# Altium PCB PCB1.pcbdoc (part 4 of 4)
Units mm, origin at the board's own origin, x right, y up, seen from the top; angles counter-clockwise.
Board outline 96.27 x 122.17 mm, 6 copper layers (Top Layer, Inner1, Inner2, Inner3, Inner4, Bottom Layer); 169 components, 166 nets, 787 pads, 477 vias.
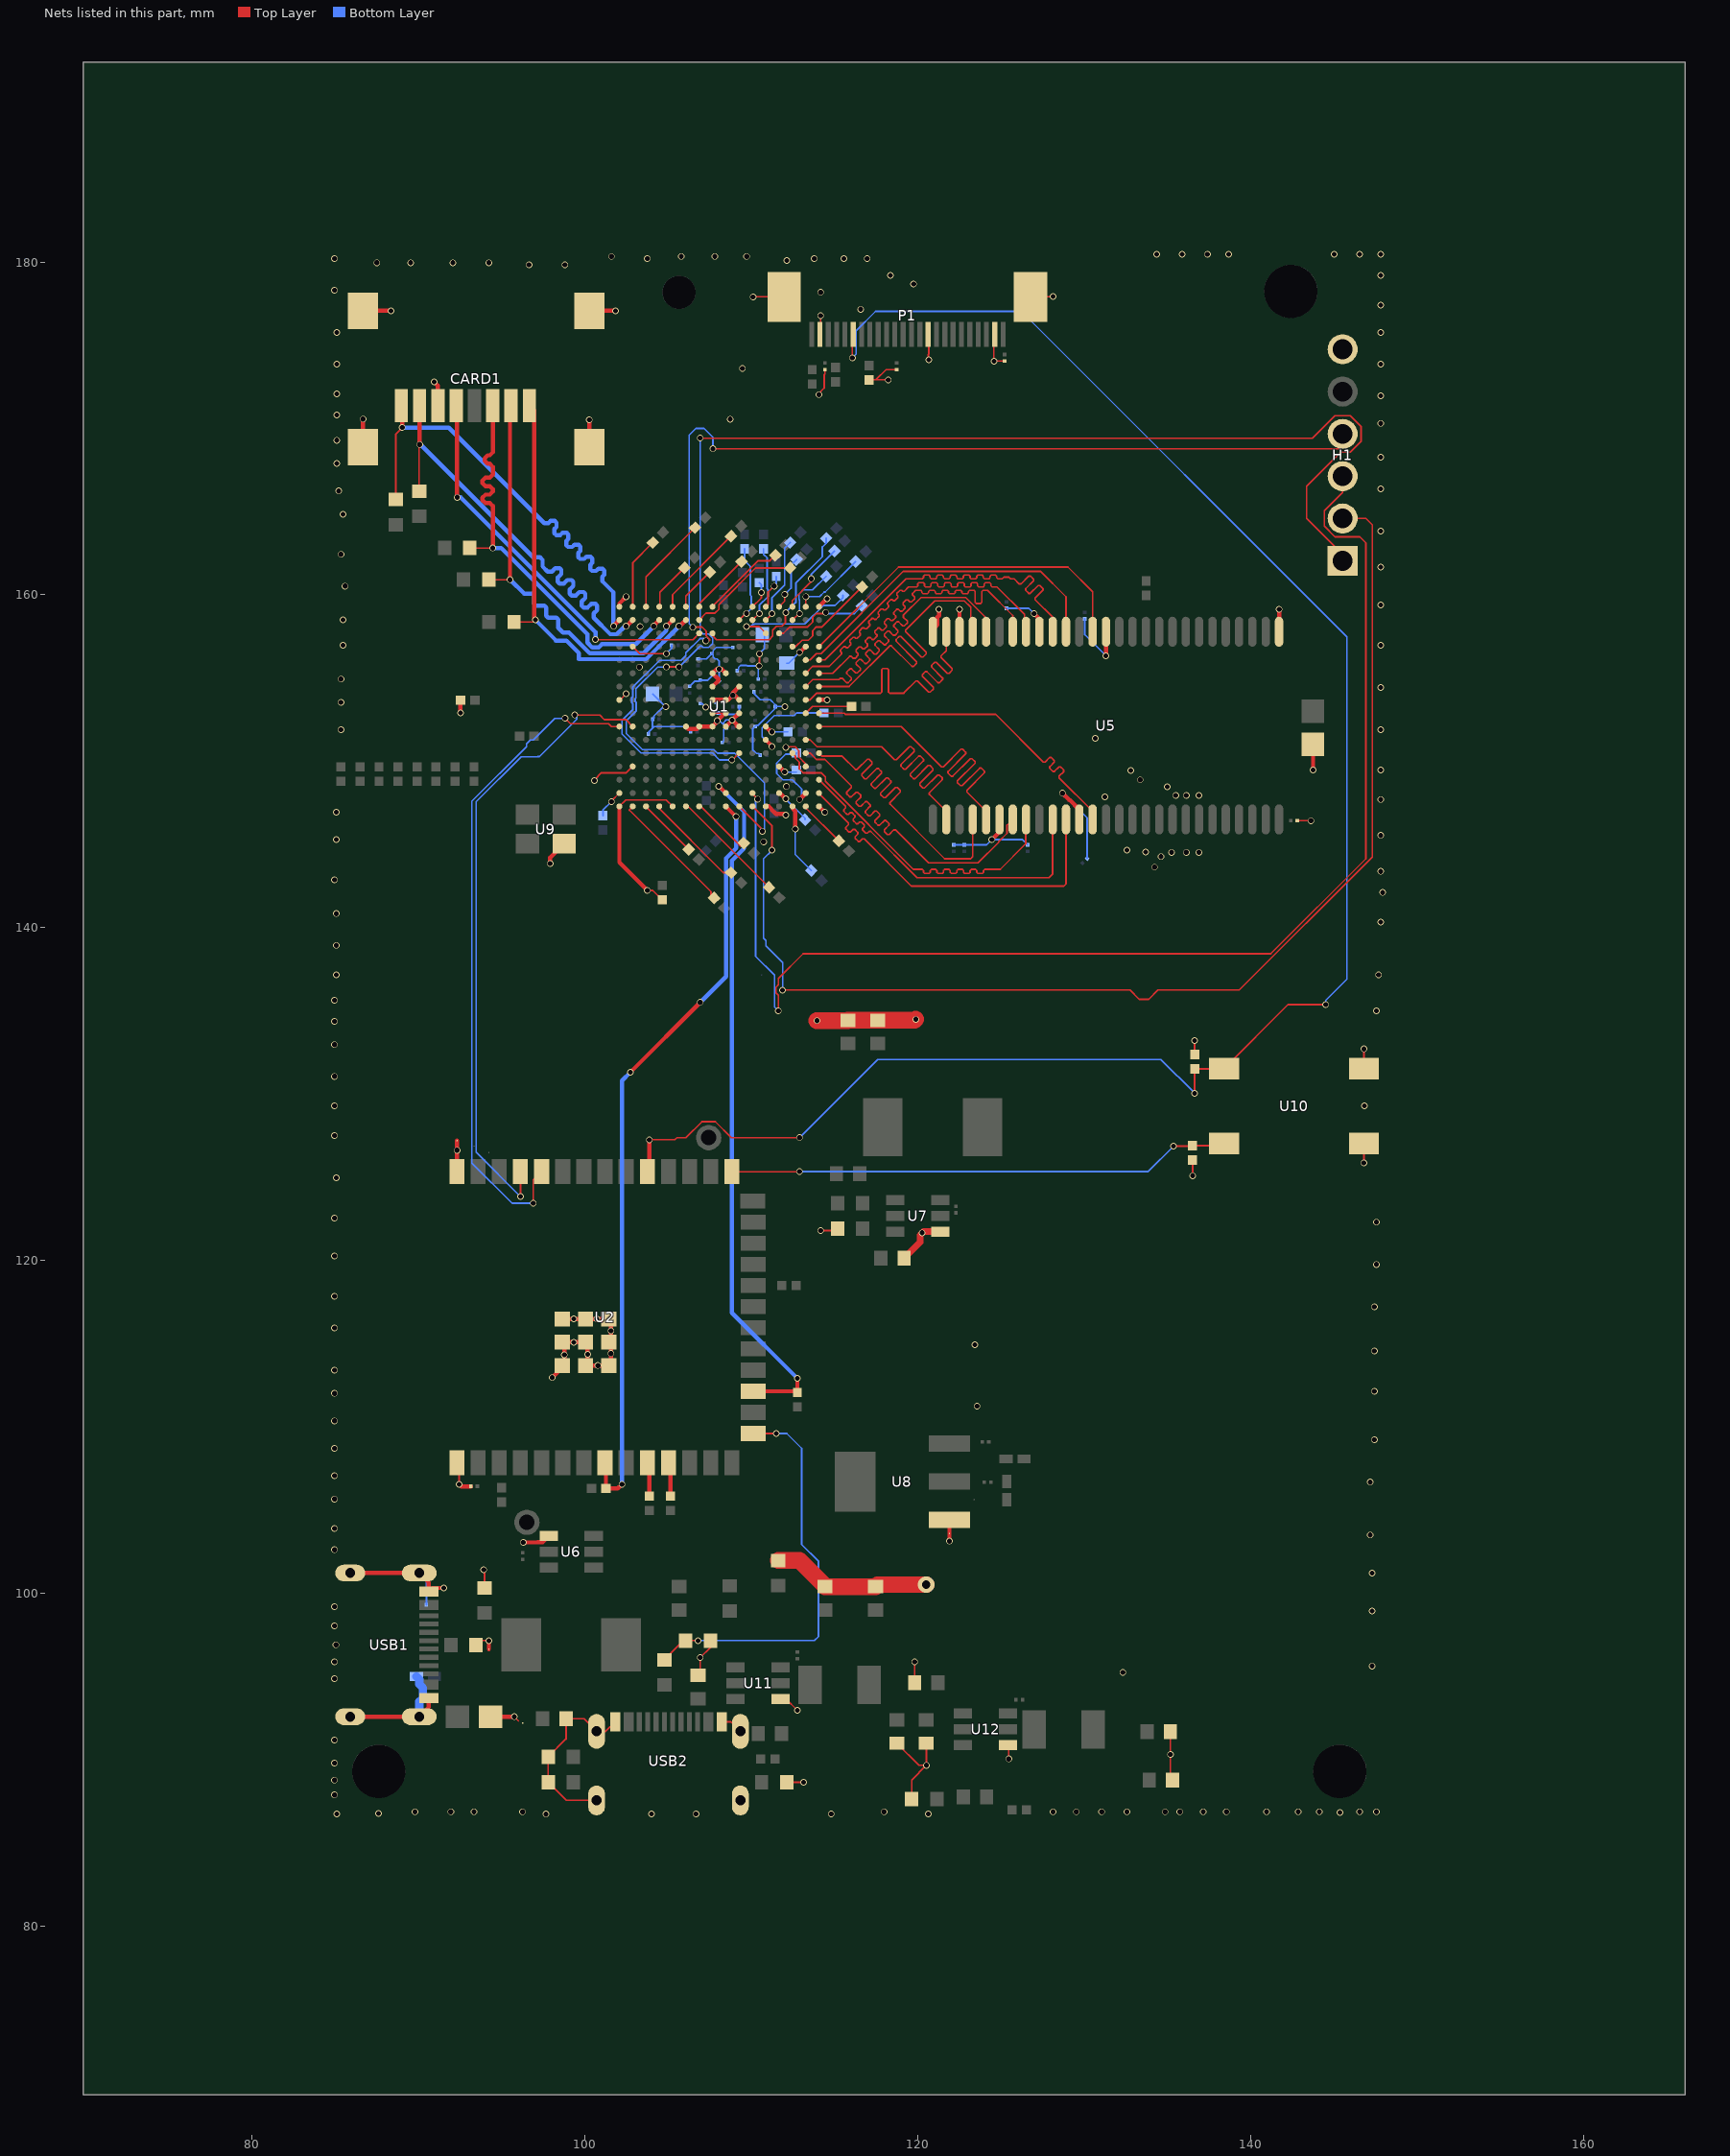
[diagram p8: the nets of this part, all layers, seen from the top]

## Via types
v1: diameter 0.4, hole 0.3, Top Layer to Bottom Layer, 448 vias
v2: diameter 1, hole 0.5, Top Layer to Bottom Layer, 28 vias
v3: diameter 0.5, hole 0.3, Top Layer to Bottom Layer, 1 vias

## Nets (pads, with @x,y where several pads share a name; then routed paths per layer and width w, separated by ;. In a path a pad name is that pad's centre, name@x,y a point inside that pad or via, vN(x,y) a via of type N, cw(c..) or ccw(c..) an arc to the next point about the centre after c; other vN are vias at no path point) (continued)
GND: C8.2 C10.2 C11.2 C12.2 C13.2 C14.2 C15.1 C16.1 C17.1 C20.1 C22.1 C23.1 C26.1 C27.1 C28.1 C33.1 C34.2 C35.2 C37.2 C39.2 C40.2 C41.2 C42.2 C43.2 C44.2 C45.2 C46.2 C47.2 C48.2 C49.2 C50.2 C51.2 C52.2 C53.2 C54.2 C55.2 C56.2 C57.2 C58.2 C59.2 C61.2 C62.2 C63.2 C66.1 C67.1 C68.1 C71.1 C72.1 C73.1 C74.2 C75.1 C76.2 CARD1.6 CARD1.9 CARD1.10 CARD1.11 CARD1.12 H1.6 P1.2 P1.15 P1.23 P1.25 P1.26 pad.55@92.324,127.195 pad.55@94.234,96.647 pad.55@96.266,92.202 pad.55@121.914,103.597 R9.1 R10.1 R12.1 R14.1 R24.1 R25.1 R35.2 R36.2 R37.2 R40.1 R42.2 R43.2 R45.1 R46.1 U1.A1 U1.A16 U1.D2 U1.D15 U1.F8 U1.F9 U1.G8 U1.G10 U1.H1 U1.H8 U1.H9 U1.H10 U1.H16 U1.J8 U1.J9 U1.J10 U1.K6 U1.K7 U1.K8 U1.K9 U1.K10 U1.N2 U1.N15 U1.T1 U1.T5 U1.T12 U1.T16 U2.1 U2.40 U2.41 U5.6 U5.12 U5.28 U5.41 U5.46 U5.52 U5.54 U6.4 U7.4 U8.1 U9.2 U10.2 U10.4 U11.4 U12.4 USB1.1 USB1.2 USB1.3 USB1.4 USB1.A1B12 USB1.B1A12 USB2.1 USB2.2 USB2.3 USB2.4 USB2.A1B12 USB2.B1A12 | length 203.8
  Top Layer w0.1: U2.1@92.324,107.836 92.451,107.709 v1(92.451,106.553) ; R10.1@93.463,96.901 93.717,97.155 v1(94.234,97.155) ; v1(93.931,101.415) 93.98,101.366 R9.1@93.98,100.321 ; v1(95.758,92.583) 96.012,92.329 ; v1(100.584,148.844) 100.584,148.886 101.005,149.307 102.495,149.307 U1.N2@102.877,149.689 ; USB2.3@100.709,87.554 98.891,87.554 R42.2@97.799,88.646 R43.2@97.799,90.17 98.871,91.242 C20.1@98.871,92.456 99.956,92.456 USB2.1@100.709,91.703 101.254,91.703 USB2.A1B12@101.829,92.278 ; U1.T1@102.077,147.289 102.459,147.671 104.895,147.671 U1.T5@105.277,147.289 ; 102.235,153.797 102.477,154.039 v1(102.477,154.051) ; U1.D2@102.877,156.889 103.302,156.464 103.512,156.464 103.519,156.471 104.635,156.471 104.642,156.464 v1@104.902,156.464 ; v1(103.759,142.24) 104.088,142.24 R25.1@104.648,141.68 ; C66.1@106.807,95.061 106.934,95.188 v1(106.934,96.139) 107.56,96.765 R45.1@107.56,97.155 ; U1.J8@107.677,152.889 U1.J9@108.42,152.889 ; USB2.B1A12@108.229,92.278 108.774,92.278 USB2.2@109.349,91.703 ; v1(110.109,177.909) P1.26@111.979,177.909 ; v1(110.477,155.737) 110.49,155.75 v1(110.49,156.464) ; U11.4@111.766,93.637 112.103,93.637 v1(112.776,92.964) ; v1(112.077,150.841) 112.216,150.841 112.246,150.871 112.635,150.871 112.859,150.647 112.859,150.258 113.277,149.84 U1.N15@113.277,149.689 ; R40.1@112.132,88.646 v1(113.157,88.646) ; v1(114.063,172.035) 114.063,172.102 114.39,172.429 114.39,173.245 114.427,173.282 C34.2@114.427,173.541 ; P1.2@114.135,175.655 114.173,175.694 v1(114.173,176.784) ; v1(114.173,121.793) 115.071,121.793 R14.1@115.198,121.92 ; R35.2@117.094,172.922 117.491,172.922 ; v1(118.237,172.922) 117.491,172.922 ; C68.1@118.745,90.994 120.077,89.662 v1(120.523,89.662) ; C35.2@118.745,173.541 118.11,173.541 117.491,172.922 ; R46.1@119.643,87.63 119.643,88.782 v1(120.523,89.662) ; C71.1@119.823,94.615 v1(119.823,95.885) ; C67.1@120.523,90.994 v1(120.523,89.662) ; P1.15@120.631,175.654 120.667,175.617 120.667,174.455 120.65,174.437 v1@120.65,174.117 ; P1.23@124.636,175.652 124.587,175.603 v1(124.587,174.045) 124.591,174.049 C74.2@125.222,174.049 ; U12.4@125.429,90.871 125.476,90.824 v1(125.476,90.043) ; P1.25@126.781,177.916 128.132,177.916 v1(128.143,177.927) ; C73.1@135.193,91.694 v1(135.193,90.323) 135.193,88.9 C72.1@135.32,88.773 ; v1(136.525,125.095) R37.2@136.525,126.036 ; R36.2@136.652,132.386 v1(136.652,133.223) ; C14.2@142.816,146.431 v1(143.637,146.431) ; v1(146.812,125.857) 146.821,125.866 U10.4@146.821,127.036 ; U10.2@146.821,131.536 v1(146.821,132.715)
  Top Layer w0.254: USB1.4@85.903,92.581 USB1.2@90.052,92.581 90.627,93.156 USB1.B1A12@90.627,93.701 ; USB1.3@85.903,101.221 USB1.1@90.052,101.221 90.627,100.646 USB1.A1B12@90.627,100.101 90.848,100.321 v1(91.526,100.321) ; CARD1.10@86.672,168.874 v1(86.672,170.565) ; CARD1.9@86.672,177.074 v1(88.357,177.074) ; v1(90.945,172.801) 91.172,172.574 CARD1.6@91.172,171.374 ; pad.55@92.324,127.195 v1(92.324,126.623) 92.324,125.463 U2.40@92.451,125.336 ; v1(92.451,106.553) 92.578,106.426 C17.1@93.15,106.426 ; v1(92.531,152.902) R24.1@92.531,153.67 ; pad.55@94.234,96.647 v1(94.234,97.155) ; C33.1@94.345,92.583 v1(95.758,92.583) ; v1(96.299,103.058) 97.161,103.058 97.171,103.068 97.466,103.068 U6.4@97.837,103.439 ; v1(97.917,143.861) 97.917,144.202 U9.2@98.763,145.048 ; v1(98.045,112.96) 98.771,113.686 v1(98.771,114.339) 98.771,115.086 v1(99.347,115.086) 100.171,115.086 v1(100.171,114.364) 100.171,113.686 v1(100.791,113.686) 101.571,113.686 v1(101.571,114.408) v1(101.571,115.77) 101.571,116.486 v1(100.722,116.486) U2.41@100.044,116.486 v1(99.347,116.486) U2.41@98.771,116.486 ; CARD1.11@100.272,168.874 v1(100.272,170.523) ; CARD1.12@100.272,177.074 v1(101.854,177.074) ; U1.T1@102.077,147.289 102.077,143.922 v1(103.759,142.24) ; U1.A1@102.077,159.289 102.077,159.481 v1(102.489,159.893) ; U1.K6@106.077,152.089 106.218,151.948 106.736,151.948 U1.K7@106.877,152.089 U1.K8@107.677,152.089 107.964,152.376 v1(107.964,152.432) 108.42,152.889 U1.J9@108.477,152.889 ; U1.H8@107.677,153.689 U1.H9@108.477,153.689 108.628,153.689 v1(108.896,153.957) ; U1.G8@107.677,154.489 108.029,154.841 108.029,154.937 U1.F8@107.677,155.289 107.931,155.543 v1(108.068,155.543) 108.223,155.543 U1.F9@108.477,155.289 ; U1.K9@108.477,152.089 108.856,152.468 v1(108.856,152.481) ; U1.K10@109.121,152.117 109.121,152.215 v1(108.856,152.481) ; U1.J10@109.277,152.889 109.264,152.889 v1(108.856,152.481) ; U1.H10@109.277,153.689 109.009,153.957 v1(108.896,153.957) ; U1.G10@109.277,154.489 108.896,154.108 v1(108.896,153.957) ; U1.T12@110.877,147.289 111.064,147.289 111.218,147.135 111.218,147.099 111.487,146.83 112.001,146.83 v1(112.074,146.757) ; v1@112.903,156.591 112.979,156.591 U1.D15@113.277,156.889 ; U1.T16@114.077,147.289 v1(114.427,146.939) ; U1.H16@114.077,153.689 v1(114.554,153.691) ; U1.A16@114.077,159.289 v1(114.554,159.766) ; U5.54@120.918,157.915 121.189,158.186 121.189,158.657 121.285,158.753 v1(121.285,159.131) ; v1(121.914,103.134) pad.55@121.914,103.597 U8.1@121.914,104.409 ; U5.52@122.518,157.915 v1(122.518,159.131) ; v1(124.46,145.288) 124.918,145.746 U5.6@124.918,146.504 ; v1(127,158.877) 127.318,158.559 U5.46@127.318,157.788 ; v1(128.702,148.082) 129.101,147.683 129.137,147.683 129.718,147.102 U5.12@129.718,146.504 ; v1(131.318,156.337) U5.41@131.318,157.915 ; U5.28@141.718,157.788 141.732,157.802 v1(141.732,159.131) ; v1(143.764,149.479) C8.2@143.764,151.019
  Top Layer w0.4: C26.1@119.191,120.142 120.142,121.093 120.142,121.524 v1@120.269,121.651 ; v1(120.269,121.666) v1@120.269,121.651 ; U7.4@121.365,121.732 120.35,121.732 v1@120.269,121.651
  Top Layer w1: R12.1@111.633,101.972 112.912,101.972 C23.1@114.489,100.395 ; v1(113.951,134.411) 115.804,134.411 C27.1@115.824,134.431 C28.1@117.602,134.431 119.826,134.431 v1(119.888,134.493) ; C23.1@114.427,100.395 C23.1@114.489,100.395 ; v2(120.515,100.522) 117.602,100.522 C22.1@117.475,100.395 C23.1@114.489,100.395
  Bottom Layer w0.1: USB1.1@90.052,101.221 90.483,100.791 C76.2@90.483,99.314 ; C51.2@103.818,151.638 103.818,151.749 104.072,152.003 ; C61.2@104.075,154.051 104.089,154.051 v1(104.864,153.276) 104.711,153.276 104.155,152.721 104.155,152.567 104.115,152.527 C56.2@104.072,152.527 104.072,152.003 ; v1(104.901,156.465) 105.215,156.779 C37.2@105.215,156.972 ; C41.2@106.299,154.5 106.612,154.813 106.875,154.813 C62.2@106.934,154.872 107.397,154.872 v1(108.068,155.543) ; C54.2@106.358,151.765 106.032,152.091 104.16,152.091 104.072,152.003 ; C63.2@106.807,156.151 107.315,156.151 C50.2@107.628,156.464 ; C45.2@106.934,153.475 107.043,153.475 v1(107.263,153.256) ; C46.2@107.882,153.543 107.935,153.49 107.935,152.991 C57.2@108.018,152.908 108.113,152.813 109.188,152.813 ; v1(107.964,152.432) 108.103,152.432 108.346,152.19 ; C42.2@108.068,154.826 v1(108.068,155.543) ; C53.2@108.263,151.13 108.346,151.213 108.346,151.919 108.446,152.019 C49.2@108.517,152.019 108.346,152.19 ; C39.2@108.898,156.845 107.898,156.845 107.711,156.658 107.711,156.547 C50.2@107.628,156.464 ; C43.2@109.152,155.448 109.235,155.531 109.235,155.642 109.353,155.76 109.731,155.76 109.754,155.737 v1(110.477,155.737) 110.422,155.682 C40.2@110.422,154.94 ; C47.2@109.288,153.289 109.288,152.913 109.188,152.813 ; C44.2@110.168,154.178 110.168,154.067 110.534,153.701 111.146,153.701 111.447,153.4 C55.2@111.447,153.289 ; v1(110.49,156.464) 110.806,156.78 C58.2@110.806,157.607 ; C48.2@110.549,150.368 110.443,150.474 110.323,150.474 110.088,150.709 110.088,151.93 C52.2@110.236,152.078 110.319,152.161 110.43,152.161 111.447,153.178 C55.2@111.447,153.289 ; v1@112.014,153.289 C55.2@111.447,153.289 ; C59.2@112.141,155.894 112.254,155.894 v1(112.903,156.544) ; C10.2@122.174,144.975 C11.2@122.809,144.975 124.147,144.975 v1(124.46,145.288) 126.306,145.288 C12.2@126.619,144.975 ; C16.1@125.349,159.19 126.687,159.19 v1(127,158.877) ; v1(128.702,148.082) 130.186,146.598 C13.2@130.186,144.156 ; C15.1@130.048,158.555 130.048,157.607 v1(131.318,156.337) ; C50.2@107.628,156.464 107.711,156.381 107.711,156.27 107.829,156.152 107.94,156.152 108.068,156.024 v1(108.068,155.543) ; 108.346,152.19 108.346,152.331 108.496,152.481 v1(108.856,152.481) 109.188,152.813
  Bottom Layer w0.5: C75.1@89.879,94.996 90.052,94.823 90.052,94.54 90.28,94.312 90.28,93.71 90.052,93.482 USB1.2@90.052,92.581
  other v1: 85.09,86.741 97.663,86.729 104.013,86.741 106.68,86.741 114.808,86.741 120.65,86.741 87.608,86.762 145.379,86.827 89.789,86.868 91.948,86.868 93.345,86.868 96.266,86.868 117.983,86.868 128.143,86.868 129.54,86.868 131.064,86.868 132.588,86.868 134.874,86.868 135.763,86.868 137.16,86.868 138.557,86.868 140.97,86.868 142.875,86.868 144.145,86.868 146.558,86.868 147.574,86.868 84.963,87.884 84.963,88.773 84.963,89.789 84.963,91.186 84.963,94.869 132.334,95.25 147.32,95.631 84.963,95.885 85.048,96.901 84.963,98.044 147.32,98.933 84.963,99.187 147.32,101.219 84.963,102.616 147.193,103.505 84.963,103.886 84.963,105.664 147.193,106.68 84.963,107.061 84.963,108.712 147.447,109.22 84.963,110.363 123.571,111.252 84.963,112.014 147.447,112.141 84.963,113.411 147.447,114.554 123.444,114.935 84.963,115.951 147.447,117.221 84.963,117.856 147.574,119.761 84.963,120.269 147.574,122.301 84.963,122.555 85.069,124.968 84.963,127.508 84.963,129.286 146.86,129.286 84.963,131.064 84.963,132.969 84.963,134.366 147.574,135.001 84.963,135.636 85.069,137.16 147.701,137.16 85.069,138.938 147.828,140.335 85.069,140.843 147.955,142.113 84.963,142.875 147.828,143.383 134.239,143.637 134.62,144.272 135.255,144.526 136.144,144.526 136.906,144.526 133.707,144.55 132.588,144.653 110.744,145.161 85.069,145.288 147.828,145.542 85.069,146.939 147.828,147.701 131.261,147.864 135.509,147.955 136.144,147.955 136.906,147.955 135.001,148.463 112.121,148.485 133.372,148.884 132.812,149.449 147.828,149.479 130.683,151.384 85.344,151.892 147.828,151.892 112.029,153.289 85.344,153.543 147.828,154.432 85.344,154.94 103.279,155.659 85.471,156.972 147.828,156.972 103.326,158.088 85.471,158.496 147.828,159.385 85.598,160.528 147.828,161.671 85.344,162.433 147.828,163.83 85.471,164.846 85.217,166.243 147.828,166.37 85.09,167.894 147.828,168.275 85.09,169.291 147.828,170.307 108.733,170.561 85.09,170.815 147.828,171.958 85.09,172.085 109.474,173.609 85.09,173.863 147.828,173.863 120.667,174.117 85.09,175.768 147.828,175.768 116.586,177.165 147.828,177.419 114.173,178.181 84.963,178.308 119.761,178.689 118.364,179.197 147.828,179.197 96.647,179.832 98.806,179.832 87.503,179.959 89.535,179.959 92.075,179.959 94.234,179.959 112.141,180.086 84.963,180.213 103.759,180.213 113.792,180.213 115.57,180.213 116.967,180.213 101.6,180.34 105.791,180.34 107.823,180.34 109.728,180.34 134.366,180.467 135.89,180.467 137.414,180.467 138.684,180.467 145.034,180.467 146.558,180.467 147.828,180.467
HREF: R75.1 U1.A11 | length 1.7
  Top Layer w0.1: U1.A11@110.077,159.289 110.617,159.829 v1(110.617,160.147)
  Bottom Layer w0.1: R75.1@110.49,160.73 110.617,160.603 v1(110.617,160.147)
INITN: pad.55@102.235,127.254 R5.1 U1.T9 U2.8 | length 46.5
  Top Layer w0.254: U2.8@101.341,107.836 101.271,107.766 R5.1@101.271,106.299 101.981,106.299 v1(102.235,106.553) ; v1(102.743,131.318) v1(106.934,135.509) ; U1.T9@108.477,147.289 109.081,146.685 v1(109.093,146.685)
  Bottom Layer w0.254: v1(102.235,106.553) pad.55@102.235,127.254 102.235,130.81 v1(102.743,131.318) ; v1(106.934,135.509) 108.485,137.06 108.485,144.172 109.093,144.78 v1(109.093,146.685)
M_CLK: CARD1.5 U1.C7 | length 24
  Top Layer w0.1: v1(100.639,157.325) 100.656,157.307 106.495,157.307 U1.C7@106.877,157.689
  Top Layer w0.254: CARD1.5@92.272,171.374 92.329,171.317 v1(92.329,165.862)
  Bottom Layer w0.254: v1(92.329,165.862) 92.541,165.862 100.639,157.764 v1(100.639,157.325)
M_CMD: CARD1.3 R20.1 U1.B4 | length 25.6
  Top Layer w0.1: R20.1@93.082,162.814 v1(94.472,162.814)
  Top Layer w0.254: v1(94.472,162.814) 94.472,165.339 94.293,165.518 94.033,165.518 93.853,165.698 93.853,165.847 94.033,166.026 94.293,166.026 94.472,166.206 94.472,166.355 94.293,166.534 94.033,166.534 93.853,166.714 93.853,166.863 94.033,167.042 94.293,167.042 94.472,167.222 94.472,167.699 94.293,167.878 94.16,167.878 93.98,168.058 93.98,168.207 94.16,168.386 94.293,168.386 94.472,168.566 CARD1.3@94.472,171.374 ; v1(104.14,158.115) 104.14,158.152 U1.B4@104.477,158.489
  Bottom Layer w0.254: v1(94.472,162.814) 94.98,162.814 100.16,157.634 100.16,157.126 100.44,156.846 100.837,156.846 101.036,157.045 103.07,157.045 v1(104.14,158.115)
M_D0: CARD1.7 R18.1 U1.B2 | length 26.9
  Top Layer w0.1: R18.1@90.043,166.234 90.043,169.008 v1(90.072,169.037)
  Top Layer w0.254: v1(90.072,169.037) CARD1.7@90.072,171.374 ; v1(102.489,158.115) 102.503,158.115 U1.B2@102.877,158.489
  Bottom Layer w0.254: v1(90.072,169.037) 90.128,169.037 96.902,162.263 97.304,162.263 97.462,162.104 97.462,161.703 97.766,161.398 98.02,161.398 98.232,161.61 98.486,161.61 98.591,161.505 98.591,161.251 98.38,161.039 98.38,160.785 98.485,160.68 98.739,160.68 98.95,160.892 99.204,160.892 99.31,160.786 99.31,160.532 99.098,160.321 99.098,160.067 99.203,159.961 99.457,159.961 99.669,160.173 99.923,160.173 100.028,160.068 100.028,159.814 99.816,159.602 99.816,159.348 99.922,159.243 100.176,159.243 100.387,159.455 100.641,159.455 100.747,159.349 100.747,159.095 100.535,158.884 100.535,158.63 101.529,157.636 101.925,157.636 102.404,158.115 v1(102.489,158.115)
M_D1: CARD1.8 R19.1 U1.B1 | length 28.5
  Top Layer w0.1: R19.1@88.646,165.726 88.646,169.672 v1(89.027,170.053)
  Top Layer w0.254: CARD1.8@88.972,171.374 89.027,171.319 v1(89.027,170.053) ; v1(101.727,158.115) 101.727,158.139 U1.B1@102.077,158.489
  Bottom Layer w0.254: v1(89.027,170.053) 91.821,170.053 97.558,164.316 97.812,164.316 97.939,164.443 98.193,164.443 98.298,164.338 98.298,164.084 98.171,163.957 98.171,163.703 98.277,163.597 98.531,163.597 98.658,163.724 98.912,163.724 99.017,163.619 99.017,163.365 98.89,163.238 98.89,162.984 98.995,162.879 99.249,162.879 99.376,163.006 99.63,163.006 99.735,162.901 99.735,162.647 99.608,162.52 99.608,162.266 99.714,162.16 99.968,162.16 100.095,162.287 100.349,162.287 100.454,162.182 100.454,161.928 100.327,161.801 100.327,161.547 100.432,161.442 100.686,161.442 100.813,161.569 101.067,161.569 101.172,161.464 101.172,161.21 101.045,161.083 101.045,160.829 101.727,160.147 v1(101.727,158.115)
M_D2: CARD1.1 R16.1 U1.B6 | length 25.4
  Top Layer w0.1: R16.1@95.876,158.369 96.901,158.369 v1(97.028,158.496)
  Top Layer w0.254: CARD1.1@96.672,171.374 96.957,171.089 96.957,158.567 v1(97.028,158.496) ; v1(105.664,158.115) 105.703,158.115 U1.B6@106.077,158.489
  Bottom Layer w0.254: v1(97.028,158.496) 98.269,157.255 98.895,157.255 99.653,156.497 99.653,156.138 103.687,156.138 v1(105.664,158.115)
M_D3: CARD1.2 R17.1 U1.B5 | length 25.2
  Top Layer w0.1: R17.1@94.225,160.909 v1(95.504,160.909)
  Top Layer w0.254: v1(95.504,160.909) 95.504,171.306 CARD1.2@95.572,171.374 ; v1(104.902,158.115) U1.B5@105.277,158.489
  Bottom Layer w0.254: v1(95.504,160.909) 95.517,160.909 96.362,160.064 96.857,160.064 96.969,159.952 96.969,159.457 97.081,159.346 97.575,159.346 97.687,159.234 97.687,158.739 97.799,158.627 98.294,158.627 98.406,158.515 98.406,158.021 98.692,157.734 99.051,157.734 100.294,156.492 103.54,156.492 104.902,157.854 v1(104.902,158.115)
MCLK: R77.1 U1.A12 | length 2.1
  Top Layer w0.1: U1.A12@110.877,159.289 111.019,159.431 111.019,160.168 v1(111.379,160.528)
  Bottom Layer w0.1: v1(111.379,160.528) 111.506,160.655 R77.1@111.506,161.111
PCLK: R80.1 U1.C8 | length 11.3
  Top Layer w0.1: U1.C8@107.677,157.689 107.677,157.548 107.918,157.307 111.079,157.307 111.295,157.523 111.295,157.883 111.519,158.107 111.835,158.107 112.059,158.331 112.059,158.919 v1(112.077,158.937)
  Bottom Layer w0.1: v1(112.077,158.937) 112.682,159.542 112.682,160.704 114.276,162.298 114.276,162.875 114.502,163.102 R80.1@114.502,163.397
PROGRAM: R37.1 U2.27 U10.3 | length 30.3
  Top Layer w0.1: U2.27@108.834,125.336 112.89,125.336 v1(112.903,125.349) ; v1(135.382,126.873) 136.497,126.873 R37.1@136.525,126.901 138.287,126.901 U10.3@138.421,127.036
  Bottom Layer w0.1: v1(112.903,125.349) 133.858,125.349 v1(135.382,126.873)
PROGRAMN: pad.55@108.839,136.377 R4.2 U1.R9 U2.17 | length 42.2
  Top Layer w0.254: v1(108.04,148.5) 108.066,148.5 U1.R9@108.477,148.089 ; U2.17@110.241,112.141 112.701,112.141 R4.2@112.776,112.066 v1(112.776,112.92)
  Bottom Layer w0.254: v1(108.04,148.5) 109.572,146.968 109.572,144.758 108.839,144.025 pad.55@108.839,136.377 108.839,116.857 v1(112.776,112.92)
RESET: P1.6 R36.1 U2.31 U10.1 | length 113.1
  Top Layer w0.1: v1(103.881,127.254) 105.41,127.254 105.537,127.381 106.079,127.381 107.043,128.345 107.841,128.345 108.805,127.381 v1(112.903,127.381) ; v1(116.078,174.244) 116.078,175.599 P1.6@116.135,175.655 ; v1(136.652,130.048) R36.1@136.652,131.52 138.405,131.52 U10.1@138.421,131.536 142.267,135.382 v1(144.526,135.382)
  Top Layer w0.254: U2.31@103.881,125.336 v1(103.881,127.254)
  Bottom Layer w0.1: v1(112.903,127.381) 117.602,132.08 134.62,132.08 v1(136.652,130.048) ; v1(116.078,174.244) 116.304,174.47 116.304,175.867 117.475,177.038 126.238,177.038 145.796,157.48 145.796,136.906 144.526,135.636 v1(144.526,135.382)
RX: U1.K1 U2.36 | length 39.7
  Top Layer w0.1: v1(96.901,123.444) 96.901,124.833 U2.36@97.404,125.336 ; v1(98.807,152.582) 99.135,152.254 101.434,152.254 101.599,152.089 U1.K1@102.077,152.089
  Bottom Layer w0.1: v1(96.901,123.444) 95.631,123.444 93.218,125.857 93.218,147.598 96.499,150.879 96.499,151.043 96.734,151.278 96.898,151.278 98.202,152.582 v1(98.807,152.582)
SCL: R21.1 U2.10 | length 1.9
  Top Layer w0.254: U2.10@103.881,107.836 103.886,107.831 R21.1@103.886,105.918
SD_A0: R56.1 U1.T6 | length 7
  Top Layer w0.1: U1.T6@106.077,147.289 106.203,147.289 R56.1@111.073,142.419
SD_A1: R57.1 U1.T4 | length 6
  Top Layer w0.1: U1.T4@104.477,147.289 104.477,147.148 108.317,143.308 R57.1@108.787,143.308
SD_A2: R58.1 U1.T3 | length 3.6
  Top Layer w0.1: U1.T3@103.677,147.289 103.677,147.275 R58.1@106.247,144.705
SD_A3: R59.1 U1.T2 | length 7.7
  Top Layer w0.1: U1.T2@102.877,147.289 102.687,147.099 102.687,147.056 107.58,142.162 107.58,141.975 R59.1@107.771,141.784
SD_A4: R68.2 U1.A2 | length 4.4
  Top Layer w0.1: U1.A2@102.877,159.289 102.891,159.303 102.891,161.946 R68.2@104.088,163.143
SD_A5: R67.2 U1.A3 | length 6
  Top Layer w0.1: U1.A3@103.677,159.289 103.677,161.081 R67.2@106.628,164.032
SD_A6: R66.2 U1.A4 | length 3
  Top Layer w0.1: U1.A4@104.477,159.289 104.521,159.333 104.521,160.147 R66.2@105.993,161.619
SD_A7: R65.2 U1.A5 | length 5.7
  Top Layer w0.1: U1.A5@105.277,159.289 105.277,160.014 R65.2@108.787,163.524
SD_A8: R64.2 U1.A6 | length 2.7
  Top Layer w0.1: U1.A6@106.077,159.289 106.077,159.925 R64.2@107.517,161.365
SD_A9: R63.2 U1.A7 | length 3.8
  Top Layer w0.1: U1.A7@106.877,159.289 106.877,159.455 R63.2@109.422,162
SD_A10: R55.1 U1.T7 | length 3.5
  Top Layer w0.1: U1.T7@106.877,147.289 106.974,147.289 R55.1@109.363,144.9
SD_A11: R62.2 U1.A8 | length 5.1
  Top Layer w0.1: U1.A8@107.677,159.289 107.677,159.312 110.417,162.052 111.125,162.052 R62.2@111.454,162.381
SD_A12: R61.2 U1.B7 | length 6.9
  Top Layer w0.1: U1.B7@106.877,158.489 107.295,158.907 107.835,158.907 108.059,159.131 108.059,159.411 110.267,161.619 R61.2@112.343,161.619
SD_BA0: R54.1 U1.K12 | length 1.5
  Top Layer w0.254: U1.K12@110.877,152.089 111.203,151.763 v1(111.25,151.763)
  Bottom Layer w0.1: v1(111.25,151.763) R54.1@112.216,151.763
SD_BA1: R53.1 U1.L12 | length 6.1
  Top Layer w0.254: U1.L12@110.877,151.289 111.252,150.914 v1(111.252,150.876)
  Bottom Layer w0.1: v1(111.252,150.876) 110.648,151.48 110.648,152.013 111.389,152.753 112.581,152.753 112.736,152.908 R53.1@114.375,152.908
SD_CAS_N: R49.1 U1.R13 | length 2.3
  Top Layer w0.254: U1.R13@111.677,148.089 111.725,148.089 v1(112.077,147.737)
  Bottom Layer w0.1: v1(112.077,147.737) 113.234,146.58 R49.1@113.234,146.485
SD_CLK: R2.2 U1.J15 | length 2.9
  Top Layer w0.1: U1.J15@113.277,152.889 113.677,153.289 R2.2@116.026,153.289
SD_CS_N: R51.1 U1.R15 | length 5.3
  Top Layer w0.254: v1(112.903,147.701) 113.277,148.075 U1.R15@113.277,148.089
  Bottom Layer w0.1: R51.1@112.724,150.495 112.658,150.429 112.075,150.429 111.535,149.889 111.535,149.262 111.911,148.887 112.479,148.887 113.03,148.336 113.03,147.701 v1(112.903,147.701)
SD_DQ0: U1.L15 U5.2 | length 20.1
  Top Layer w0.1: U1.L15@113.277,151.289 113.537,151.289 113.955,150.871 117.84,150.871 118.62,150.091 118.72,150.091 119.505,150.877 119.605,150.877 119.788,150.694 119.788,150.594 119.003,149.808 119.003,149.708 119.186,149.526 119.286,149.526 120.071,150.311 120.171,150.311 120.354,150.128 120.354,150.028 119.568,149.243 119.568,149.143 119.751,148.96 119.851,148.96 120.637,149.745 120.737,149.745 120.92,149.562 120.92,149.463 120.134,148.677 120.134,148.577 120.317,148.394 120.417,148.394 121.202,149.18 121.302,149.18 121.485,148.997 121.485,148.897 120.7,148.111 120.7,148.011 121.718,146.993 U5.2@121.718,146.504
SD_DQ1: U1.M16 U5.4 | length 21.6
  Top Layer w0.1: U1.M16@114.077,150.489 114.259,150.307 115.465,150.307 116.263,149.509 116.363,149.509 116.981,150.127 117.081,150.127 117.264,149.944 117.264,149.844 116.646,149.226 116.646,149.126 116.828,148.943 116.928,148.943 117.547,149.561 117.647,149.561 117.83,149.378 117.83,149.278 117.211,148.66 117.211,148.56 117.394,148.377 117.494,148.377 118.112,148.996 118.212,148.996 118.395,148.813 118.395,148.713 117.777,148.094 117.777,147.994 117.96,147.812 118.06,147.812 118.678,148.43 118.778,148.43 118.961,148.247 118.961,148.147 118.343,147.529 118.343,147.429 121.626,144.145 123.19,144.145 123.318,144.273 U5.4@123.318,146.504
SD_DQ2: U1.K16 U5.5 | length 22
  Top Layer w0.1: U1.K16@114.077,152.089 119.022,152.089 121.445,149.666 121.545,149.666 122.604,150.724 122.704,150.724 122.887,150.541 122.887,150.441 121.828,149.383 121.828,149.283 122.011,149.1 122.111,149.1 123.17,150.159 123.27,150.159 123.452,149.976 123.452,149.876 122.394,148.817 122.394,148.717 122.577,148.534 122.677,148.534 123.735,149.593 123.835,149.593 124.018,149.41 124.018,149.31 122.96,148.252 122.96,148.152 124.118,146.993 U5.5@124.118,146.504
SD_DQ3: U1.M15 U5.7 | length 21.1
  Top Layer w0.1: U1.M15@113.277,150.489 113.537,150.489 113.919,150.107 114.434,150.107 116.02,148.521 116.02,148.421 115.739,148.14 115.739,148.04 115.922,147.857 116.022,147.857 116.303,148.138 116.403,148.138 116.585,147.956 116.585,147.856 116.304,147.575 116.304,147.475 116.487,147.292 116.587,147.292 116.868,147.573 116.968,147.573 117.151,147.39 117.151,147.29 116.87,147.009 116.87,146.909 117.053,146.726 117.153,146.726 117.434,147.007 117.534,147.007 117.717,146.824 117.717,146.724 117.436,146.443 117.436,146.343 117.619,146.16 117.719,146.16 118,146.441 118.1,146.441 118.282,146.259 118.282,146.159 118.001,145.878 118.001,145.778 118.184,145.595 118.284,145.595 118.565,145.876 118.665,145.876 120.65,143.891 123.632,143.891 124.862,145.121 124.862,145.159 125.37,145.667 125.37,146.156 U5.7@125.718,146.504
SD_DQ4: U1.M14 U5.8 | length 21.2
  Top Layer w0.1: U1.M14@112.477,150.489 112.659,150.307 112.659,150.175 112.895,149.939 112.895,149.531 113.119,149.307 114.199,149.307 114.459,149.047 114.459,148.79 119.739,143.51 120.288,143.51 120.358,143.439 120.358,143.327 120.429,143.256 120.688,143.256 120.758,143.327 120.758,143.439 120.829,143.51 121.088,143.51 121.158,143.439 121.158,143.327 121.229,143.256 121.488,143.256 121.558,143.327 121.558,143.439 121.629,143.51 121.888,143.51 121.958,143.439 121.958,143.327 122.029,143.256 122.288,143.256 122.358,143.327 122.358,143.439 122.429,143.51 122.688,143.51 122.758,143.439 122.758,143.327 122.829,143.256 123.088,143.256 123.158,143.327 123.158,143.439 123.229,143.51 123.488,143.51 123.558,143.439 123.558,143.327 123.629,143.256 123.888,143.256 123.958,143.327 123.958,143.439 124.029,143.51 124.968,143.51 126.492,145.034 126.492,146.478 U5.8@126.518,146.504
SD_DQ5: U1.P16 U5.10 | length 21
  Top Layer w0.1: U1.P16@114.077,148.889 115.669,147.297 115.669,147.197 115.569,147.097 115.569,146.997 115.752,146.814 115.852,146.814 115.952,146.914 116.052,146.914 116.235,146.731 116.235,146.631 116.135,146.531 116.135,146.431 116.318,146.249 116.418,146.249 116.518,146.348 116.618,146.348 116.8,146.166 116.8,146.066 116.701,145.966 116.701,145.866 116.884,145.683 116.984,145.683 117.083,145.783 117.183,145.783 119.964,143.002 127.889,143.002 128.118,143.231 U5.10@128.118,146.504
SD_DQ6: U1.R16 U5.11 | length 22
  Top Layer w0.1: U1.R16@114.173,147.955 115.841,146.287 115.841,146.187 115.687,146.033 115.687,145.933 115.87,145.75 115.97,145.75 116.124,145.904 116.224,145.904 116.406,145.722 116.406,145.622 116.252,145.468 116.252,145.368 116.435,145.185 116.535,145.185 116.689,145.339 116.789,145.339 119.634,142.494 128.778,142.494 128.918,142.634 U5.11@128.918,146.504
SD_DQ7: U1.J16 U5.13 | length 21.2
  Top Layer w0.1: U1.J16@114.077,152.889 115.588,152.889 115.66,152.817 124.694,152.817 127.557,149.954 127.657,149.954 127.93,150.227 128.03,150.227 128.213,150.044 128.213,149.944 127.94,149.671 127.94,149.571 128.123,149.388 128.223,149.388 128.496,149.661 128.596,149.661 128.779,149.478 128.779,149.378 128.506,149.105 128.506,149.005 130.518,146.993 U5.13@130.518,146.504
SD_DQ8: U1.D16 U5.42 | length 21.4
  Top Layer w0.1: U1.D16@114.077,156.889 118.859,161.671 129.032,161.671 130.518,160.185 U5.42@130.518,157.788
SD_DQ9: U1.E15 U5.44 | length 20.6
  Top Layer w0.1: U1.E15@113.277,156.089 113.537,156.089 113.919,156.471 114.199,156.471 119.145,161.417 127.381,161.417 128.918,159.88 U5.44@128.918,157.788
SD_DQ10: U1.E16 U5.45 | length 22.6
  Top Layer w0.1: U1.E16@114.077,156.089 114.433,156.089 119.307,160.963 120.282,160.963 120.352,161.034 120.352,161.117 120.423,161.188 120.682,161.188 120.752,161.117 120.752,161.034 120.823,160.963 121.082,160.963 121.152,161.034 121.152,161.117 121.223,161.188 121.482,161.188 121.552,161.117 121.552,161.034 121.623,160.963 121.882,160.963 121.952,161.034 121.952,161.117 122.023,161.188 122.282,161.188 122.352,161.117 122.352,161.034 122.423,160.963 122.682,160.963 122.752,161.034 122.752,161.117 122.823,161.188 123.082,161.188 123.152,161.117 123.152,161.034 123.223,160.963 123.482,160.963 123.552,161.034 123.552,161.117 123.623,161.188 123.882,161.188 123.952,161.117 123.952,161.034 124.023,160.963 124.282,160.963 124.352,161.034 124.352,161.117 124.423,161.188 124.682,161.188 124.752,161.117 124.752,161.034 124.823,160.963 125.082,160.963 125.182,161.063 125.482,161.063 125.582,160.963 125.803,160.963 126.111,160.655 126.211,160.655 126.682,161.127 126.782,161.127 126.965,160.944 126.965,160.844 126.494,160.372 126.494,160.272 126.677,160.089 126.777,160.089 127.248,160.561 127.348,160.561 127.531,160.378 127.531,160.278 127.06,159.806 127.06,159.706 128.118,158.648 U5.45@128.118,157.788
SD_DQ11: U1.F15 U5.47 | length 21.1
  Top Layer w0.1: U1.F15@113.277,155.289 113.69,155.702 114.681,155.702 115.424,156.445 115.424,156.545 115.368,156.6 115.368,156.7 115.551,156.883 115.651,156.883 115.707,156.828 115.807,156.828 115.99,157.011 115.99,157.111 115.934,157.166 115.934,157.266 116.117,157.449 116.217,157.449 116.272,157.393 116.372,157.393 116.555,157.576 116.555,157.676 116.5,157.732 116.5,157.832 116.683,158.014 116.783,158.014 116.838,157.959 116.938,157.959 117.121,158.142 117.121,158.242 117.066,158.297 117.066,158.397 117.248,158.58 117.348,158.58 117.404,158.525 117.504,158.525 117.687,158.708 117.687,158.808 117.631,158.863 117.631,158.963 117.814,159.146 117.914,159.146 117.969,159.09 118.069,159.09 118.252,159.273 118.252,159.373 118.197,159.429 118.197,159.529 118.38,159.712 118.48,159.712 118.535,159.656 118.635,159.656 118.818,159.839 118.818,159.939 118.763,159.994 118.763,160.094 118.945,160.277 119.045,160.277 119.101,160.222 119.201,160.222 119.453,160.474 119.936,160.474 120.007,160.545 120.007,160.663 120.078,160.734 120.336,160.734 120.407,160.663 120.407,160.545 120.478,160.474 120.736,160.474 120.807,160.545 120.807,160.663 120.878,160.734 121.136,160.734 121.207,160.663 121.207,160.545 121.278,160.474 121.536,160.474 121.607,160.545 121.607,160.663 121.678,160.734 121.936,160.734 122.007,160.663 122.007,160.545 122.078,160.474 122.336,160.474 122.407,160.545 122.407,160.663 122.478,160.734 122.736,160.734 122.807,160.663 122.807,160.545 122.878,160.474 123.136,160.474 123.207,160.545 123.207,160.663 123.278,160.734 123.536,160.734 123.607,160.663 123.607,160.545 123.678,160.474 123.936,160.474 124.007,160.545 124.007,160.663 124.078,160.734 124.336,160.734 124.407,160.663 124.407,160.545 124.478,160.474 124.768,160.474 126.418,158.824 126.418,157.888 U5.47@126.518,157.788
SD_DQ12: U1.F16 U5.48 | length 20.9
  Top Layer w0.1: U1.F16@114.077,155.289 114.903,155.289 115.92,156.306 116.02,156.306 116.139,156.187 116.239,156.187 116.422,156.37 116.422,156.47 116.303,156.589 116.303,156.689 116.486,156.872 116.586,156.872 116.704,156.753 116.804,156.753 116.987,156.936 116.987,157.036 116.868,157.154 116.868,157.254 117.051,157.437 117.151,157.437 117.27,157.318 117.37,157.318 117.553,157.501 117.553,157.601 117.434,157.72 117.434,157.82 117.617,158.003 117.717,158.003 117.836,157.884 117.936,157.884 118.119,158.067 118.119,158.167 118,158.286 118,158.386 118.183,158.569 118.283,158.569 118.402,158.45 118.502,158.45 118.684,158.633 118.684,158.733 118.565,158.851 118.565,158.951 118.748,159.134 118.848,159.134 118.967,159.015 119.067,159.015 119.25,159.198 119.25,159.298 119.131,159.417 119.131,159.517 119.314,159.7 119.414,159.7 119.533,159.581 119.633,159.581 119.816,159.764 119.816,159.864 119.697,159.983 119.697,160.083 119.888,160.274 120.188,160.274 120.259,160.203 120.259,160.139 120.329,160.068 120.588,160.068 120.659,160.139 120.659,160.203 120.729,160.274 120.988,160.274 121.059,160.203 121.059,160.139 121.129,160.068 121.388,160.068 121.459,160.139 121.459,160.203 121.529,160.274 121.788,160.274 121.859,160.203 121.859,160.139 121.929,160.068 122.188,160.068 122.259,160.139 122.259,160.203 122.329,160.274 122.588,160.274 122.659,160.203 122.659,160.139 122.729,160.068 122.988,160.068 123.059,160.139 123.059,160.203 123.129,160.274 123.388,160.274 123.459,160.203 123.459,159.555 123.529,159.484 123.788,159.484 123.859,159.555 123.859,160.203 123.929,160.274 124.206,160.274 125.718,158.762 U5.48@125.718,157.788
SD_DQ13: U1.G15 U5.50 | length 20.1
  Top Layer w0.1: U1.G15@113.277,154.489 113.695,154.907 115.283,154.907 115.364,154.988 115.464,154.988 115.727,154.724 115.827,154.724 116.01,154.907 116.01,155.007 115.747,155.271 115.747,155.371 115.929,155.553 116.029,155.553 116.275,155.307 116.375,155.307 116.558,155.49 116.558,155.59 116.312,155.836 116.312,155.936 116.495,156.119 116.595,156.119 116.841,155.873 116.941,155.873 117.124,156.056 117.124,156.156 116.878,156.402 116.878,156.502 117.061,156.685 117.161,156.685 117.407,156.439 117.507,156.439 117.689,156.622 117.689,156.722 117.444,156.968 117.444,157.068 117.626,157.25 117.726,157.25 117.972,157.005 118.072,157.005 118.255,157.187 118.255,157.287 118.009,157.533 118.009,157.633 118.192,157.816 118.292,157.816 118.538,157.57 118.638,157.57 118.821,157.753 118.821,157.853 118.575,158.099 118.575,158.199 118.758,158.382 118.858,158.382 119.104,158.136 119.204,158.136 119.386,158.319 119.386,158.419 119.141,158.665 119.141,158.765 120.215,159.839 122.892,159.839 124.118,158.613 U5.50@124.118,157.788
SD_DQ14: U1.G16 U5.51 | length 20.1
  Top Layer w0.1: U1.G16@114.077,154.489 115.881,154.489 118.328,156.936 118.428,156.936 119.661,155.702 119.761,155.702 119.944,155.885 119.944,155.985 118.711,157.219 118.711,157.319 118.894,157.502 118.994,157.502 120.227,156.268 120.327,156.268 120.51,156.451 120.51,156.551 119.276,157.784 119.276,157.884 121.031,159.639 122.809,159.639 123.19,159.258 123.19,157.916 U5.51@123.318,157.788
SD_DQ15: U1.H15 U5.53 | length 19.6
  Top Layer w0.1: U1.H15@113.277,153.689 113.537,153.689 113.941,154.093 117.775,154.093 117.846,154.164 117.846,155.504 117.917,155.575 118.175,155.575 118.246,155.504 118.246,154.164 118.317,154.093 119.168,154.093 119.895,154.82 119.995,154.82 120.657,154.158 120.757,154.158 120.94,154.341 120.94,154.441 120.278,155.103 120.278,155.203 120.461,155.386 120.561,155.386 121.223,154.724 121.323,154.724 121.506,154.907 121.506,155.007 120.844,155.669 120.844,155.769 121.026,155.951 121.126,155.951 121.788,155.289 121.888,155.289 122.071,155.472 122.071,155.572 121.409,156.234 121.409,156.334 121.718,156.643 U5.53@121.718,157.788
SD_DQM0: R69.1 U1.T15 | length 2.9
  Top Layer w0.1: U1.T15@113.277,147.289 113.277,147.2 R69.1@115.264,145.213
SD_DQM1: R70.2 U1.D14 | length 5.9
  Top Layer w0.1: U1.D14@112.477,156.889 112.68,156.889 113.062,157.271 113.435,157.271 113.695,157.531 113.695,157.847 113.919,158.071 114.256,158.071 R70.2@116.661,160.476
SD_RAS_N: R50.1 U1.T14 | length 4.1
  Top Layer w0.254: U1.T14@112.522,147.123 112.649,146.996 v1(112.649,145.923)
  Bottom Layer w0.1: v1(112.649,145.923) 112.649,144.399 R50.1@113.613,143.435
SD_WE_N: R48.1 U1.N13 | length 1.2
  Top Layer w0.254: U1.N13@111.677,149.689 v1(112.014,149.352)
  Bottom Layer w0.1: v1(112.014,149.352) R48.1@112.724,149.352
SDA: R22.1 U2.11 | length 1.9
  Top Layer w0.254: R22.1@105.151,105.918 U2.11@105.151,107.836
SSPI_CS_N: R86.1 U1.R1 | length 1.8
  Top Layer w0.1: v1(101.6,147.574) 101.6,147.612 U1.R1@102.077,148.089
  Bottom Layer w0.1: R86.1@101.092,146.737 101.092,147.066 v1(101.6,147.574)
TCK: H1.1 U1.T10 | length 87.4
  Top Layer w0.1: v1(104.898,155.661) 105.109,155.661 105.119,155.671 105.435,155.671 105.445,155.661 105.623,155.661 v1@105.664,155.702 ; v1(106.934,169.418) 143.73,169.418 145.086,170.774 145.998,170.774 146.644,170.128 146.644,169.216 145.998,168.57 145.422,168.57 143.383,166.531 143.383,164.592 145.542,162.433 H1.1@145.542,162.052 ; U1.T10@109.277,147.289 110.661,145.905 v1(110.661,145.796)
  Bottom Layer w0.1: v1(104.898,155.661) 104.382,155.661 103.079,154.358 103.079,153.802 103.03,153.752 103.03,153.6 103.091,153.538 103.091,153.04 102.489,152.438 102.489,151.667 103.461,150.695 107.76,150.695 107.973,150.481 109.006,150.481 110.792,148.695 110.792,145.927 v1(110.661,145.796) ; v1(105.664,155.661) 106.934,156.931 107.019,156.931 107.111,156.839 107.444,156.839 107.679,157.075 107.679,157.408 107.444,157.643 107.111,157.643 106.934,157.82 v1(106.934,169.418)
TDI: H1.3 U1.R11 | length 79.6
  Top Layer w0.1: U1.R11@110.077,148.089 110.077,148.041 v1(110.39,147.728) ; v1(111.633,135.001) 111.633,135.935 111.485,136.083 111.485,136.417 111.633,136.565 111.633,136.946 113.117,138.43 141.224,138.43 146.939,144.145 146.939,163.13 146.579,163.49 145.086,163.49 144.44,164.136 144.44,165.048 145.542,166.15 H1.3@145.542,167.132
  Bottom Layer w0.1: v1(110.39,147.728) 110.259,147.597 110.259,138.291 111.402,137.148 111.402,135.232 v1(111.633,135.001)
TDO: H1.4 U1.M10 | length 70.3
  Top Layer w0.1: v1(106.489,158.054) 106.701,158.054 106.719,158.071 107.035,158.071 107.295,157.811 107.295,157.531 107.519,157.307 107.519,157.271 107.489,157.241 v1(107.277,157.241) ; v1(107.696,168.783) 145.288,168.783 ; v1(108.839,150.079) 108.867,150.079 U1.M10@109.277,150.489
  Bottom Layer w0.1: v1(106.489,158.054) 106.278,158.265 106.278,169.601 106.678,170.001 107.159,170.001 107.696,169.464 v1(107.696,168.783) ; v1(107.277,157.241) 107.15,157.368 106.921,157.368 106.066,156.514 106.066,156.357 105.772,156.063 104.501,156.063 102.879,154.441 102.879,153.884 102.83,153.835 102.83,153.517 102.891,153.456 102.891,153.122 102.235,152.466 102.235,151.638 103.378,150.495 107.677,150.495 108.092,150.079 v1(108.839,150.079)
TMS: H1.2 U1.T11 | length 73.3
  Top Layer w0.1: U1.T11@110.077,147.289 111.252,146.114 v1(111.252,144.653) ; v1(111.887,136.25) 132.759,136.25 133.313,135.696 133.895,135.696 134.449,136.25 139.327,136.25 147.32,144.243 147.32,164.211 146.939,164.592 H1.2@145.542,164.592
  Bottom Layer w0.1: v1(111.252,144.653) 110.744,144.145 110.744,139.38 110.892,139.232 110.892,138.898 111.887,137.903 v1(111.887,136.25)
TX: U1.K2 U2.37 | length 38.6
  Top Layer w0.1: v1@96.134,123.825 U2.37@96.134,125.336 ; v1@99.314,152.781 100.904,152.781 101.179,152.506 102.458,152.506 ; 102.459,152.507 U1.K2@102.877,152.089
  Bottom Layer w0.1: v1(96.134,123.846) 93.472,126.508 93.472,147.57 96.176,150.274 97.15,150.274 97.157,150.281 97.27,150.281 99.509,152.52 99.509,152.661 v1(99.389,152.781)
USB_VBUS: R44.1 R45.2 U2.15 | length 24.9
  Top Layer w0.1: R44.1@104.775,96.003 105.927,97.155 R45.2@106.054,97.155 v1(106.805,97.155) ; U2.15@110.114,109.601 v1(111.506,109.601)
  Bottom Layer w0.1: v1(106.805,97.155) 113.792,97.155 114.046,97.409 114.046,101.917 113.03,102.933 113.03,108.712 112.141,109.601 v1(111.506,109.601)
VSYNC: R73.1 U1.B10 | length 4.8
  Top Layer w0.1: U1.B10@109.277,158.489 109.673,158.885 v1(109.72,158.885)
  Bottom Layer w0.1: R73.1@109.601,162.762 109.601,162.053 109.946,161.708 109.946,159.99 110.003,159.933 110.003,159.167 v1(109.72,158.885)
Y2: R82.1 U1.B14 | length 3.8
  Top Layer w0.1: U1.B14@112.477,158.489 112.865,158.877 v1(112.903,158.877)
  Bottom Layer w0.1: v1(112.903,158.877) 112.903,159.705 112.882,159.726 112.882,160.06 113.117,160.295 113.686,160.295 R82.1@114.502,161.111
Y3: R84.1 U1.C12 | length 8
  Top Layer w0.1: v1(109.714,158.1) 110.466,158.1 U1.C12@110.877,157.689
  Bottom Layer w0.1: v1(109.714,158.1) 109.967,158.1 110.109,158.242 110.178,158.242 110.195,158.259 113.231,158.259 114.336,159.364 115.041,159.364 115.518,159.841 R84.1@115.518,159.968
Y4: R85.1 U1.C13 | length 5.9
  Top Layer w0.1: U1.C13@111.677,157.689 111.937,157.689 112.319,158.071 113.399,158.071 113.695,158.367 113.695,158.647 113.919,158.871 114.411,158.871 v1(114.486,158.945)
  Bottom Layer w0.1: v1(114.486,158.945) 114.554,158.877 116.205,158.877 R85.1@116.661,159.333
Y5: R83.1 U1.A15 | length 4.5
  Top Layer w0.1: U1.A15@113.277,159.289 113.284,159.296 v1(113.284,159.893)
  Bottom Layer w0.1: v1(113.284,159.893) 114.112,159.893 114.387,160.168 114.448,160.168 R83.1@116.28,162
Y6: R81.1 U1.A14 | length 4.4
  Top Layer w0.1: U1.A14@112.477,159.289 112.477,159.655 113.603,160.781 v1(113.603,160.968)
  Bottom Layer w0.1: v1(113.603,160.968) 113.603,161.228 R81.1@115.01,162.635
Y7: R79.1 U1.A13 | length 3.3
  Top Layer w0.1: U1.A13@111.677,159.289 112.014,159.626 v1(112.014,160.02)
  Bottom Layer w0.1: v1(112.014,160.02) 112.395,160.401 112.395,161.798 R79.1@112.724,162.127
Y8: R78.1 U1.B12 | length 5.3
  Top Layer w0.1: U1.B12@110.877,158.489 111.252,158.864 v1(111.252,158.877)
  Bottom Layer w0.1: v1(111.252,158.877) 111.252,159.832 112.016,160.596 112.016,162.816 R78.1@112.343,163.143
Y9: R76.1 U1.B11 | length 4.8
  Top Layer w0.1: U1.B11@110.077,158.489 110.465,158.877 v1(110.49,158.877)
  Bottom Layer w0.1: v1(110.49,158.877) 110.49,159.385 111.019,159.914 111.019,160.314 110.962,160.371 110.962,162.215 110.744,162.433 R76.1@110.744,162.762
pads on no net: P1.1 P1.10 SCREW1.1 SCREW2.1 SCREW3.1 SCREW4.1 U1.A9 U1.B3 U1.B8 U1.B13 U1.B15 U1.B16 U1.C1 U1.C2 U1.C3 U1.C4 U1.C5 U1.C6 U1.C9 U1.C10 U1.C11 U1.C14 U1.C15 U1.C16 U1.D1 U1.D3 U1.D4 U1.D5 U1.D6 U1.D7 U1.D8 U1.D9 U1.D10 U1.D11 U1.D12 U1.D13 U1.E3 U1.E4 U1.E5 U1.E6 U1.E7 U1.E8 U1.E9 U1.E10 U1.E11 U1.E12 U1.E13 U1.E14 U1.F3 U1.F4 U1.F5 U1.F12 U1.F13 U1.F14 U1.G3 U1.G4 U1.G5 U1.G12 U1.G13 U1.G14 U1.H2 U1.H3 U1.H4 U1.H5 U1.H12 U1.H13 U1.H14 U1.J3 U1.J4 U1.J5 U1.J12 U1.J13 U1.J14 U1.K3 U1.K4 U1.K5 U1.K13 U1.K14 U1.K15 U1.L1 U1.L2 U1.L3 U1.L4 U1.L5 U1.L13 U1.L14 U1.L16 U1.M2 U1.M3 U1.M4 U1.M5 U1.M6 U1.M7 U1.M9 U1.M11 U1.M12 U1.M13 U1.N1 U1.N3 U1.N4 U1.N5 U1.N6 U1.N7 U1.N8 U1.N9 U1.N11 U1.N12 U1.N14 U1.N16 U1.P1 U1.P2 U1.P3 U1.P4 U1.P5 U1.P6 U1.P7 U1.P8 U1.P12 U1.P13 U1.P14 U1.P15 U1.R2 U1.R3 U1.R4 U1.R5 U1.R6 U1.R7 U1.R8 U1.R12 U1.R14 U1.T13 U2.4 U2.16 U2.26 U2.28 U2.29 U2.30 U2.32 U2.33 U2.34 U2.35 U2.38 U2.39 U5.40 U8.4 USB1.A6 USB1.A7 USB1.A8 USB1.B6 USB1.B7 USB1.B8 USB2.A8 USB2.B6 USB2.B7 USB2.B8
copper on no net: | length 13
  Top Layer w0.1: 93.345,126.873 93.594,126.624 93.594,125.336 ; 94.234,126.492 94.864,125.862 94.864,125.336 ; 96.134,107.836 96.363,107.607 v1(96.363,106.202) ; 105.024,125.336 105.024,125.971 106.561,127.508 107.188,127.508 107.442,127.254
  Top Layer w0.254: v1(101.473,148.54) 101.728,148.54 102.077,148.889 ; v1(103.272,149.246) 103.272,149.284 103.677,149.689 ; v1(104.029,148.489) 104.077,148.489 104.477,148.889 ; v1(104.14,149.352) 104.477,149.689
  Bottom Layer w0.1: v1(96.363,106.202) 96.363,104.424 96.52,104.267

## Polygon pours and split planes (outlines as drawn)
+5V on Inner3 (solid, remove dead copper): 82.831,122.963 132.342,122.963 132.342,85.821 82.831,85.821
GND on Inner1 (solid, remove dead copper): 76.2,182.626 151.257,182.626 151.257,78.486 76.2,78.486
+5V on Top Layer (solid, remove dead copper, pour order 0): 86.741,99.695 89.878,99.695 89.878,93.641 86.741,93.641
+3V3 on Inner2 (solid, remove dead copper): 77.597,185.674 159.766,185.674 159.766,76.2 77.597,76.2
GND on Inner4 (solid, remove dead copper): 78.549,185.084 153.606,185.084 153.606,80.944 78.549,80.944
+1V1 on Inner3 (solid, remove dead copper): 78.93,184.406 153.987,184.406 153.987,80.266 78.93,80.266

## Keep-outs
Inner2:
  region: 84.455,156.364 93.124,156.364 93.124,105.664 84.455,105.664
Inner3:
  region: 84.692,156.414 93.362,156.414 93.362,105.714 84.692,105.714
Board Outline Layer:
  lines w0.254: 84.455,86.229 148.455,86.229 148.455,181.229 84.455,181.229 84.455,86.229

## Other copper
Top Layer:
  region net GND: 92.073,127.396 92.581,127.396 92.581,126.995 92.067,126.995 92.073,127
  region net GND: 93.983,96.848 94.491,96.848 94.491,96.446 93.977,96.446 93.983,96.452
  region net GND: 96.015,92.403 96.523,92.403 96.523,92.001 96.009,92.001 96.015,92.007
  region net +1V8: 123.143,105.828 123.651,105.828 123.651,105.426 123.138,105.426 123.143,105.431
  region net GND: 121.662,103.797 122.17,103.797 122.17,103.396 121.657,103.396 121.662,103.401
  region: 93.094,127.074 93.602,127.074 93.602,126.672 93.088,126.672 93.094,126.678
  region: 93.983,126.693 94.491,126.693 94.491,126.291 93.977,126.291 93.983,126.297
Bottom Layer:
  region net DONE: 110.366,137.361 110.874,137.361 110.874,136.959 110.36,136.959 110.366,136.965
  region net PROGRAMN: 108.588,136.577 109.096,136.577 109.096,136.176 108.582,136.176 108.588,136.181
  region net INITN: 101.984,127.455 102.492,127.455 102.492,127.053 101.978,127.053 101.984,127.059

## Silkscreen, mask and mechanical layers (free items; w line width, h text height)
Top Silkscreen Layer:
  text "JTAG" at 144.674,166.326 h3.05 r90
